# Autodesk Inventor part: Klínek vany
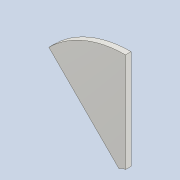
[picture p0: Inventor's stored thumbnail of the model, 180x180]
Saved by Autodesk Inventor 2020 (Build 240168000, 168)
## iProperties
Created: 2025-03
Part Number: Klínek vany
Material: Ocel
Document SubType Name: Modeling
Designer: doma
Density: 7.85 g/cm^3
Appearance: Ocel
Author: doma
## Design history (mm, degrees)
sketch "Náčrt1" dims "d0" = 5.2, "d1" = 62
  geometry: L1 (0, 31)-(0, 2.6); L2 (0, 0)-(-27.468, 27.468); L3 (0, 0)-(38.846, 0); 4 further points
  constraints: 6 end point, 2 coincident, 1 equal length, 1 horizontal, 1 vertical, 6 other
  dimensions: "d2" = 135 deg angle of L3 L2
extrude "Vysunutí1" new body sketch "Náčrt1" distance "d3" = 1.6; taper "d4" = 0 deg
node "Těleso1"
